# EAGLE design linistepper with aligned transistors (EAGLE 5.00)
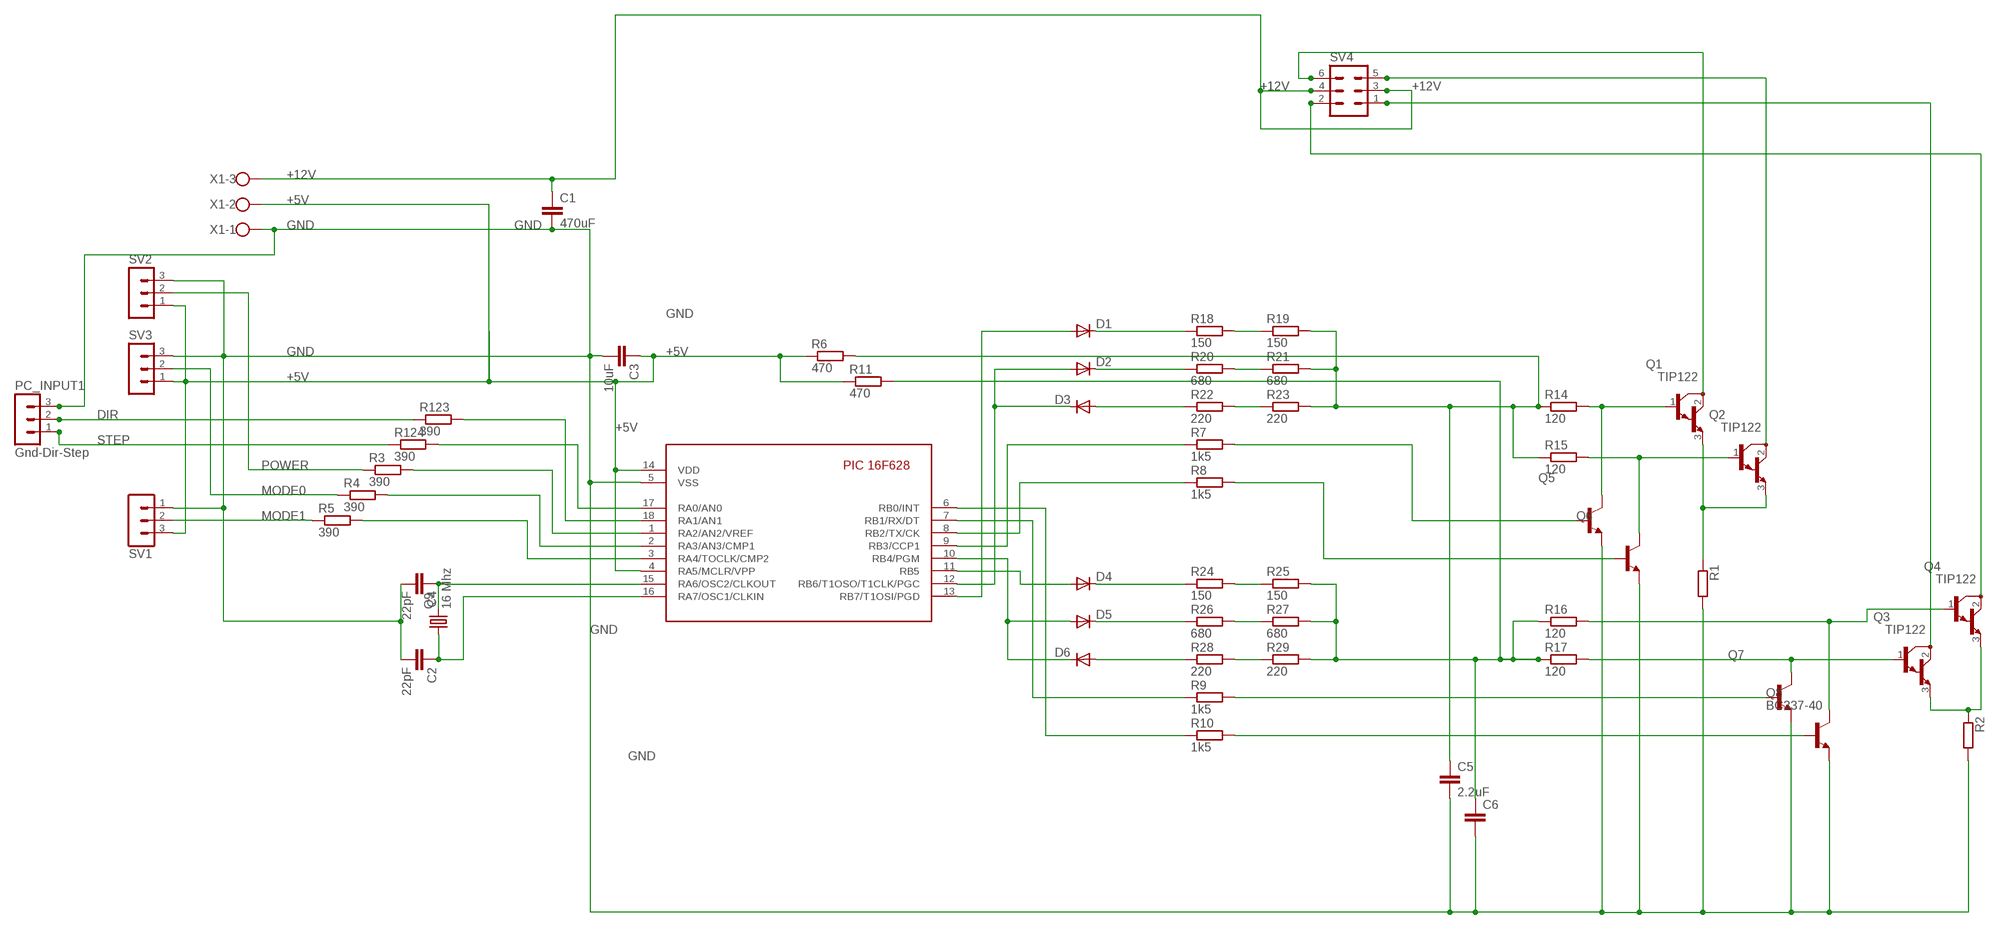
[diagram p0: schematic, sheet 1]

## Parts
C1  470uF  C-EU050-045X075  [C050-045X075]
C2  22pF  C-EU025-024X044  [C025-024X044]
C3  10uF  C-EU025-040X050  [C025-040X050]
C4  22pF  C-EU025-024X044  [C025-024X044]
C5  2.2uF  C-EU050-024X044  [C050-024X044]
C6  C-EU050-024X044  [C050-024X044]
D1  1N4148  [DO35-10]
D2  1N4148  [DO35-10]
D3  1N4148  [DO35-10]
D4  1N4148  [DO35-10]
D5  1N4148  [DO35-10]
D6  1N4148  [DO35-10]
PC_INPUT1  Gnd-Dir-Step  MA03-1  [MA03-1]
Q1  TIP122  [TO220]
Q2  TIP122  [TO220]
Q3  TIP122  [TO220]
Q4  TIP122  [TO220]
Q5  BC337-40  [TO92]
Q6  BC337-40  [TO92]
Q7  BC337-40  [TO92]
Q8  BC337-40  [TO92]
Q9  16 Mhz  CRYTALHC49S  [HC49/S]
R1  R-EU_0922/22  [0922/22]
R2  R-EU_0922/22  [0922/22]
R3  390  R-EU_0204/7  [0204/7]
R4  390  R-EU_0204/7  [0204/7]
R5  390  R-EU_0207/5V  [0207/5V]
R6  470  R-EU_0207/10  [0207/10]
R7  1k5  R-EU_0207/10  [0207/10]
R8  1k5  R-EU_0207/10  [0207/10]
R9  1k5  R-EU_0207/10  [0207/10]
R10  1k5  R-EU_0207/10  [0207/10]
R11  470  R-EU_0207/12  [0207/12]
R14  120  R-EU_0207/10  [0207/10]
R15  120  R-EU_0207/10  [0207/10]
R16  120  R-EU_0207/10  [0207/10]
R17  120  R-EU_0207/10  [0207/10]
R18  150  R-EU_0207/2V  [0207/2V]
R19  150  R-EU_0207/2V  [0207/2V]
R20  680  R-EU_0207/2V  [0207/2V]
R21  680  R-EU_0207/2V  [0207/2V]
R22  220  R-EU_0207/2V  [0207/2V]
R23  220  R-EU_0207/2V  [0207/2V]
R24  150  R-EU_0207/2V  [0207/2V]
R25  150  R-EU_0207/2V  [0207/2V]
R26  680  R-EU_0207/2V  [0207/2V]
R27  680  R-EU_0207/2V  [0207/2V]
R28  220  R-EU_0207/2V  [0207/2V]
R29  220  R-EU_0207/2V  [0207/2V]
R123  390  R-EU_0207/2V  [0207/2V]
R124  390  R-EU_0207/2V  [0207/2V]
SV1  MA03-1  [MA03-1]
SV2  MA03-1  [MA03-1]
SV3  MA03-1  [MA03-1]
SV4  MA03-2  [MA03-2]
U$1  16F628  [PIC16F628-18-LEAD-PDIP]
X1  W237-103  [W237-103]

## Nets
+5V: C3.1 R6.1 R11.1 SV1.3 SV2.1 SV3.1 U$1.4(RA5/MCLR/VPP) U$1.14(VDD) X1.2
+12V: C1.1 SV4.3 SV4.4 X1.3
DIR: PC_INPUT1.2 R123.1
GND: C1.2 C2.2 C3.2 C4.2 C5.2 C6.2 PC_INPUT1.3 Q5.1(E) Q6.1(E) Q7.1(E) Q8.1(E) R1.2 R2.2 SV1.1 SV2.3 SV3.3 U$1.5(VSS) X1.1
MODE0: R4.1 SV3.2
MODE1: R5.1 SV1.2
N$1: R18.2 R19.1
N$2: C5.1 R6.2 R14.1 R15.1 R19.2 R21.2 R23.2
N$3: R20.2 R21.1
N$5: Q1.1(B) Q5.3(C) R14.2
N$6: Q2.1(B) Q6.3(C) R15.2
N$7: D1.C R18.1
N$8: D2.C R20.1
N$9: D3.A R22.1
N$10: D1.A U$1.13(RB7/T1OSI/PGD)
N$11: D2.A D3.C U$1.12(RB6/T1OSO/T1CLK/PGC)
N$12: R8.1 U$1.8(RB2/TX/CK)
N$13: R7.1 U$1.9(RB3/CCP1)
N$14: Q5.2(B) R7.2
N$15: Q6.2(B) R8.2
N$16: Q1.3(E) Q2.3(E) R1.1
N$17: R3.2 U$1.1(RA2/AN2/VREF)
N$18: R4.2 U$1.2(RA3/AN3/CMP1)
N$19: R24.2 R25.1
N$20: D5.C R26.1
N$21: R26.2 R27.1
N$22: D6.A R28.1
N$23: R28.2 R29.1
N$24: D4.A U$1.11(RB5)
N$25: D5.A D6.C U$1.10(RB4/PGM)
N$26: R9.1 U$1.7(RB1/RX/DT)
N$27: R10.1 U$1.6(RB0/INT)
N$28: C6.1 R11.2 R16.1 R17.1 R25.2 R27.2 R29.2
N$29: Q4.1(B) Q8.3(C) R16.2
N$30: Q8.2(B) R10.2
N$31: Q3.1(B) Q7.3(C) R17.2
N$32: Q7.2(B) R9.2
N$33: Q3.3(E) Q4.3(E) R2.1
N$34: Q1.2(C) SV4.6
N$35: Q2.2(C) SV4.5
N$36: Q3.2(C) SV4.1
N$37: Q4.2(C) SV4.2
N$39: R124.2 U$1.17(RA0/AN0)
N$41: R123.2 U$1.18(RA1/AN1)
N$43: C2.1 Q9.1 U$1.16(RA7/OSC1/CLKIN)
N$44: C4.1 Q9.2 U$1.15(RA6/OSC2/CLKOUT)
N$48: R5.2 U$1.3(RA4/TOCLK/CMP2)
POWER: R3.1 SV2.2
R23: R22.2 R23.1
R24: D4.C R24.1
STEP: PC_INPUT1.1 R124.1

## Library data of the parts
C1-C6 = rcl:C-EU: CAPACITOR, European symbol
D1-D6 = diode:1N4148: DIODE
PC_INPUT1 SV1-SV3 = con-lstb:MA03-1: PIN HEADER
Q1-Q4 = transistor-npn:TIP122*: NPN Darlington Transistor
Q5-Q8 = transistor-npn:BC337*: NPN Transistor
Q9 = crystal:CRYTAL: CRYSTAL
R1-R11 R14-R29 R123 R124 = rcl:R-EU_: RESISTOR, European symbol
SV4 = con-lstb:MA03-2: PIN HEADER
U$1 = pic16f6xx:16F628: Microchip component PIC 16F628 Eric Magraner - eric_magraner@yahoo.fr 03/2004
X1 = con-wago-500:W237-103: WAGO SCREW CLAMP

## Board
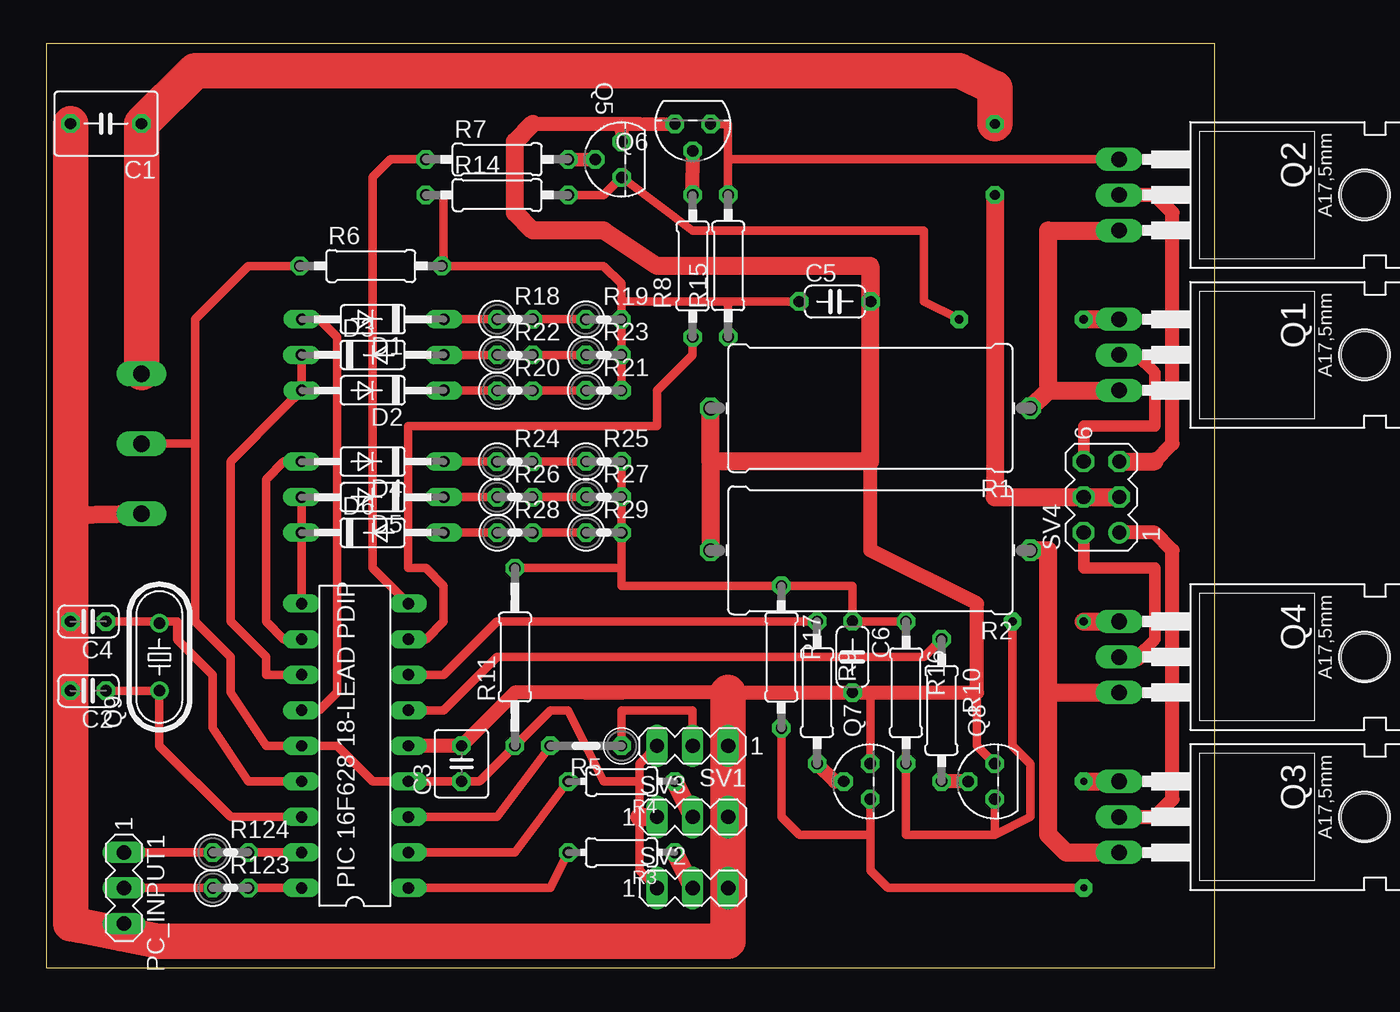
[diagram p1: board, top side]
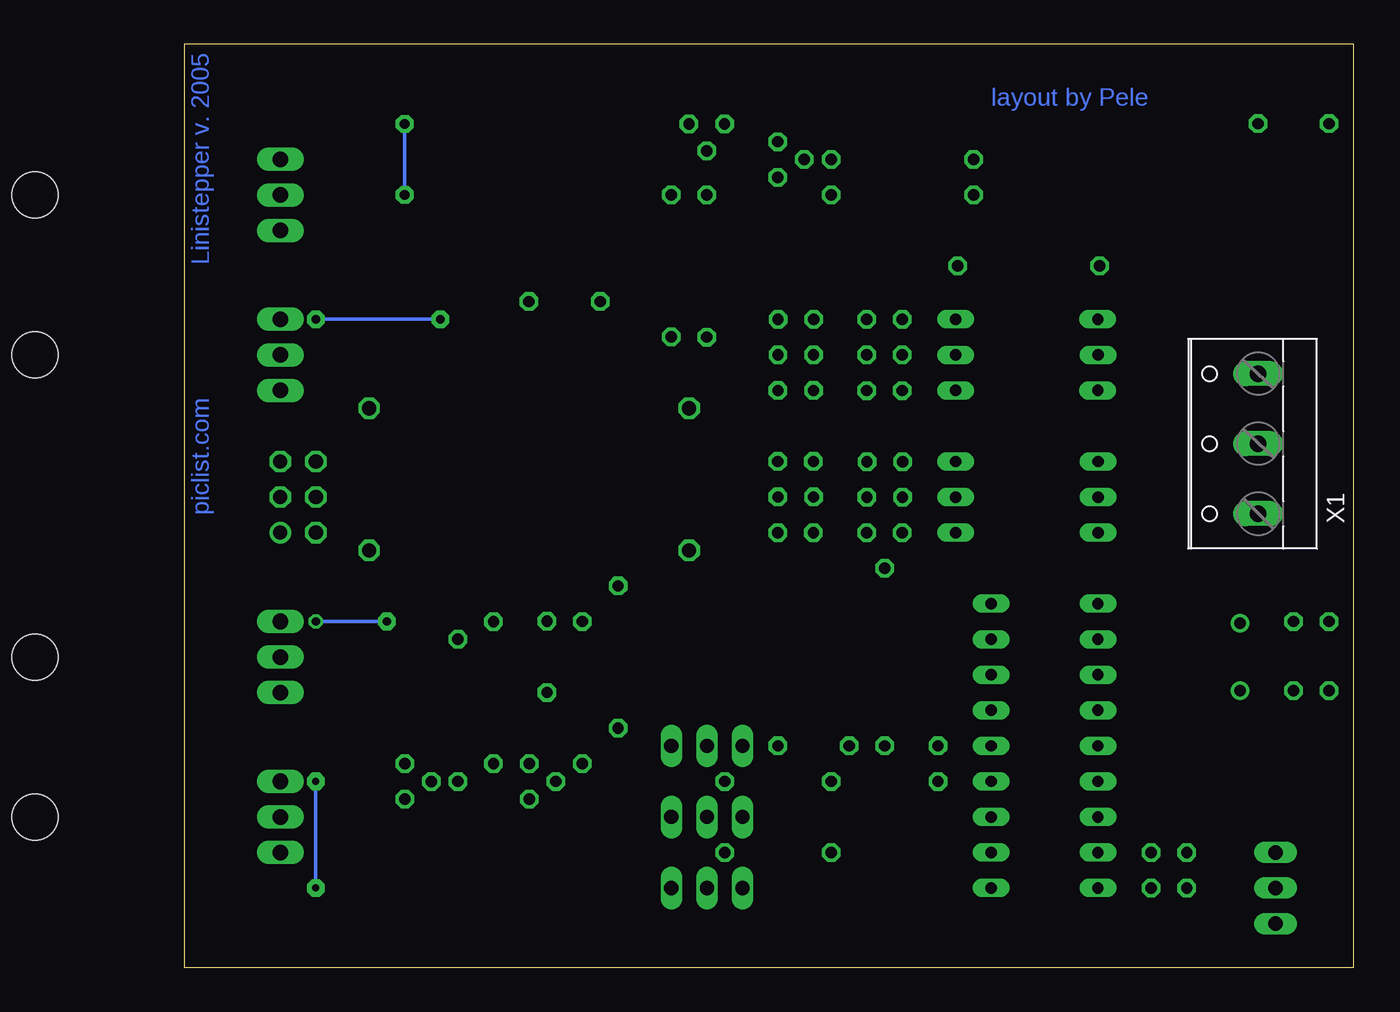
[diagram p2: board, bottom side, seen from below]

Size 83.49 x 66.03 mm. Coordinates in mm from the lower left corner, seen from the top.
Outline: 0,0 83.49,0 83.49,66.03 0,66.03 0,0
Copper layers (1*16): Top 0.035mm / dielectric 1.5mm / Bottom 0.035mm
Design rules "default": minimum track width 10mil, minimum drill 24mil, track to track 8mil, track to pad 8mil, pad to pad 8mil, via to via 8mil, smd to smd 8mil, copper to edge 40mil, drill to drill 8mil, minimum pad ring 10mil, minimum via ring 8mil, stop-mask expansion 4mil, vias tented up to drill 0mil, thermal gap 10mil

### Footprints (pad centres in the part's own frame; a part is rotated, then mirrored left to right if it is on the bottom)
C050-045X075 = drill 0.813 octagon: 1 -2.54,0; 2 2.54,0
C025-024X044 = drill 0.813 octagon: 1 -1.27,0; 2 1.27,0
C025-040X050 = drill 0.813 octagon: 1 -1.27,0; 2 1.27,0
C050-024X044 = drill 0.813 octagon: 1 -2.54,0; 2 2.54,0
DO35-10 = drill 0.813 long: A 5.08,0; C -5.08,0
MA03-1 = drill 1.016 long: 1 -2.54,0; 2 0,0; 3 2.54,0
TO220 = drill 1.118 long: 1 -2.54,-6.35; 2 0,-6.35; 3 2.54,-6.35 | hole 3.302: 0,11.176
TO92 = drill 0.813 octagon: 1 1.27,0; 2 0,1.905; 3 -1.27,0
HC49/S = drill 0.813 round: 1 -2.413,0; 2 2.413,0
0922/22 = drill 1.016 octagon: 1 -11.43,0; 2 11.43,0
0204/7 = drill 0.813 octagon: 1 -3.81,0; 2 3.81,0
0207/5V = drill 0.813 octagon: 1 -2.54,0; 2 2.54,0
0207/10 = drill 0.813 octagon: 1 -5.08,0; 2 5.08,0
0207/12 = drill 0.813 octagon: 1 -6.35,0; 2 6.35,0
0207/2V = drill 0.813 octagon: 1 -1.27,0; 2 1.27,0
MA03-2 = drill 1.016 round: 1 -2.54,-1.27 | drill 1.016 octagon: 2 -2.54,1.27; 3 0,-1.27; 4 0,1.27; 5 2.54,-1.27; 6 2.54,1.27
PIC16F628-18-LEAD-PDIP = drill 0.813 long: 1 -10.16,-3.81; 2 -7.62,-3.81; 3 -5.08,-3.81; 4 -2.54,-3.81; 5 0,-3.81; 6 2.54,-3.81; 7 5.08,-3.81; 8 7.62,-3.81; 9 10.16,-3.81; 10 10.16,3.81; 11 7.62,3.81; 12 5.08,3.81; 13 2.54,3.81; 14 0,3.81; 15 -2.54,3.81; 16 -5.08,3.81; 17 -7.62,3.81; 18 -10.16,3.81
W237-103 = drill 1.194 long: 1 -5,-1.29; 2 0,-1.29; 3 5,-1.29

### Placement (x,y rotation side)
C1  4.27,60.34 180 top
C2  3.01,19.81 180 top
C3  29.68,14.6 90 top
C4  3.01,24.76 180 top
C5  56.36,47.62 0 top
C6  57.61,22.23 270 top
D1  23.34,46.35 180 top
D2  23.33,41.27 180 top
D3  23.32,43.81 0 top
D4  23.33,36.19 180 top
D5  23.33,33.64 180 top
D6  23.32,31.11 0 top
PC_INPUT1  5.55,5.71 270 top
Q1  83.02,43.81 270 top
Q2  83.02,55.24 270 top
Q3  83.02,10.79 270 top
Q4  83.02,22.22 270 top
Q5  41.13,57.77 90.1 top
Q6  46.2,60.3 180 top
Q7  58.89,13.33 90 top
Q8  67.78,13.33 90 top
Q9  8.09,22.22 90 top
R1  58.89,40 180 top
R2  58.89,29.84 180 top
R3  41.11,8.25 180 top
R4  41.11,13.33 180 top
R5  38.57,15.87 180 top
R6  23.2,50.16 0 top
R7  32.22,57.78 0 top
R8  46.19,50.16 90 top
R9  55.08,19.68 270 top
R10  63.97,18.41 270 top
R11  33.49,22.22 90 top
R14  32.22,55.23 0 top
R15  48.73,50.18 90 top
R16  61.43,19.68 270 top
R17  52.53,22.22 270 top
R18  33.49,46.36 0 top
R19  39.84,46.34 0 top
R20  33.49,41.26 0 top
R21  39.84,41.26 0 top
R22  33.5,43.81 0 top
R23  39.84,43.81 0 top
R24  33.48,36.18 0 top
R25  39.85,36.19 0 top
R26  33.49,33.65 0 top
R27  39.84,33.66 0 top
R28  33.49,31.11 0 top
R29  39.84,31.1 0 top
R123  13.17,5.71 0 top
R124  13.17,8.25 0 top
SV1  46.19,15.87 180 top
SV2  46.19,5.71 0 top
SV3  46.19,10.79 0 top
SV4  75.4,33.65 90 top
U$1  22.06,15.87 90 top
X1  8.09,37.46 90 bottom

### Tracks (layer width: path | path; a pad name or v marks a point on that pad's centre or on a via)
+5V
  Top 0.254: R6.1 18.25,50.16
  Top 0.61: R6.1 14.44,50.16 10.63,46.35 10.63,37.46 | 10.63,37.46 X1.2 | 10.63,37.46 10.63,24.76 13.17,22.22 13.17,19.68 15.71,15.87 U$1.14 20.79,15.87 23.33,13.33 U$1.4 C3.1 30.95,13.33 R11.1 36.03,18.41 37.3,18.41 39.84,13.33 42.38,13.33 | SV2.1 42.38,6.98 42.38,10.79 42.38,13.33 | SV1.3 42.38,14.6 42.38,13.33
  Top 1.27: 42.38,10.79 SV3.1
+12V  (via drill 0.6, 0.7 pad 1.27)
  Top 0.254: C1.1
  Top 0.61: X1.3 v6.82,42.54
  Top 1.27: v67.78,55.24 67.78,33.65 SV4.4 SV4.3
  Top 2.54: v6.82,42.54 C1.1 10.63,64.13 65.24,64.13 67.78,62.86 v67.78,60.32
  Bottom 0.254: v67.78,60.32 v67.78,55.24
DIR
  Top 0.61: PC_INPUT1.2 R123.1
GND
  Top 0.254: X1.1 5.55,32.38 | 5.4,2.44 PC_INPUT1.3
  Top 0.406: 48.73,1.9 SV2.3
  Top 0.61: Q7.1 58.89,18.41 58.89,19.68 C6.2 | 66.51,19.68 66.51,15.87 Q8.1 | C1.2
  Top 1.016: U$1.5 C3.2 33.49,19.68 38.57,19.68 | 38.57,19.68 48.73,19.68 58.89,19.68 66.51,19.68 66.51,26.03 58.89,29.84 58.89,36.19 | 38.57,19.68 41.11,19.68 | 41.11,60.32 42.38,60.32 Q6.1 | 41.11,60.32 Q5.1 | 34.76,60.32 41.11,60.32
  Top 1.27: 47.46,36.19 R2.2 | 47.46,36.19 58.89,36.19 58.89,50.16 | 47.46,36.19 R1.2 | 58.89,50.16 C5.2 | 1.74,32.38 X1.1 | 34.76,60.32 33.49,59.05 33.49,53.97 34.76,52.7 39.84,52.7 43.65,50.16 58.89,50.16
  Top 2.54: C1.2 1.74,32.38 C4.2 C2.2 1.74,3.17 5.4,2.44 8.09,1.9 48.73,1.9 SV3.3 SV1.1 48.73,19.68
MODE0
  Top 1.27: SV3.2 R4.1
MODE1
  Top 0.61: SV1.2 46.19,18.41 41.11,18.41 R5.1
N$1
  Top 0.254: R19.1
  Top 0.61: R19.1 R18.2
N$2
  Top 0.254: 48.73,47.62 48.74,46.34 | R21.2 | 39.84,50.16 33.49,50.16 R6.2 | R23.2 R19.2 | R15.1 48.73,46.35
  Top 0.406: 48.73,47.62 R15.1 | R23.2 41.11,42.54
  Top 0.61: 41.11,47.62 48.73,47.62 | R21.2 41.11,42.54 R23.2 | 41.11,47.62 41.11,48.89 39.84,50.16 28.41,50.16 28.41,55.24 R14.1 | 41.11,47.62 R23.2 | 48.73,47.62 48.73,46.35 | 48.73,47.62 C5.1
N$3
  Top 0.254: R21.1
  Top 0.61: R20.2 R21.1
N$5  (via drill 0.6 pad 1.27)
  Top 0.61: R14.2 39.84,55.23 39.84,55.24 41.11,56.51 | 41.11,56.51 46.19,52.7 62.7,52.7 62.7,47.62 v65.24,46.35 | 41.11,56.51 Q5.3
  Top 1.27: v74.13,46.35 Q1.1
  Bottom 0.254: v65.24,46.35 v74.13,46.35
N$6
  Top 0.61: R15.2 48.73,57.78 | Q6.3 48.72,60.3 48.73,57.78 | 48.73,57.78 Q2.1
N$7
  Top 0.61: D1.C 29.68,46.35 30.95,46.35 R18.1
N$8
  Top 0.61: D2.C 29.68,41.27 30.95,41.27 R20.1
N$9
  Top 0.61: R22.1 30.95,43.81 29.68,43.81 D3.A
N$10
  Top 0.61: U$1.13 19.52,18.41 20.79,19.68 20.79,45.08 19.52,46.35 D1.A
N$11
  Top 0.254: D2.A
  Top 0.61: D2.A 18.25,42.54 D3.C | U$1.12 15.71,20.95 15.71,22.22 13.17,24.76 13.17,36.19 16.98,40 D2.A
N$12
  Top 0.61: U$1.8 27.14,23.49 28.41,24.76 28.41,27.3 27.14,28.57 25.87,28.57 25.87,38.73 43.65,38.73 43.65,41.27 46.19,43.81 R8.1
N$13
  Top 0.61: U$1.9 23.33,28.57 23.33,56.51 24.6,57.78 R7.1
N$14
  Top 1.016: R7.2 Q5.2
N$15
  Top 1.016: R8.2 Q6.2
N$16
  Top 1.27: 71.59,41.27 Q1.3 | R1.1 71.59,41.27 | 71.59,41.27 71.59,52.7 Q2.3
N$17
  Top 0.61: U$1.1 36.03,5.71 R3.2
N$18
  Top 0.61: U$1.2 33.49,8.25 R4.2
N$19
  Top 0.254: R25.1
  Top 0.61: R24.2 R25.1
N$20
  Top 0.61: D5.C 29.68,33.65 30.95,33.65 R26.1
N$21
  Top 0.254: R27.1
  Top 0.61: R26.2 R27.1
N$22
  Top 0.61: D6.A 29.68,31.11 30.95,31.11 R28.1
N$23
  Top 0.254: R29.1
  Top 0.61: R28.2 R29.1
N$24
  Top 0.61: U$1.11 16.98,23.49 15.71,24.76 15.71,34.92 16.98,36.19 D4.A
N$25
  Top 0.254: D5.A | D6.C
  Top 0.61: U$1.10 D6.C D5.A
N$26
  Top 0.61: U$1.7 28.41,20.95 32.22,24.76 R9.1
N$27
  Top 0.61: R10.1 62.7,22.22 32.22,22.22 28.41,18.41 U$1.6
N$28
  Top 0.254: R25.2 | R29.2 | C6.1
  Top 0.61: R25.2 R27.2 R29.2 41.11,28.57 | R16.1 C6.1 57.62,27.3 | 57.62,27.3 R17.1 | R11.2 41.11,28.57 | 41.11,28.57 41.11,27.3 57.62,27.3
N$29  (via drill 0.6 pad 0.81, 0.6 pad 1.27)
  Top 0.61: 67.78,9.52 61.43,9.52 R16.2 | 67.78,9.52 Q8.3 | 67.78,9.52 70.32,10.79 70.32,14.6 69.05,15.87 v69.05,24.76
  Top 1.27: v74.13,24.76 Q4.1
  Bottom 0.254: v69.05,24.76 v74.13,24.76
N$30
  Top 0.61: R10.2
  Top 1.016: Q8.2 R10.2
N$31  (via drill 0.5 pad 1.27)
  Top 0.61: 58.89,9.52 53.81,9.52 52.54,10.79 R17.2 | 58.89,9.52 Q7.3 | 58.89,9.52 58.89,6.98 60.16,5.71 v74.13,5.71
  Top 1.27: v74.13,13.33 Q3.1
  Bottom 0.254: v74.13,5.71 v74.13,13.33
N$32
  Top 0.61: 56.35,13.33 Q7.2 | R9.2 55.71,13.97
  Top 1.016: R9.2 56.35,13.33
N$33
  Top 1.27: 71.59,19.68 71.59,29.84 R2.1 | 71.59,19.68 71.59,9.52 72.86,8.25 Q3.3 | 71.59,19.68 Q4.3
N$34
  Top 0.813: Q1.2 77.94,43.81 79.21,42.54 79.21,38.73 74.13,38.73 SV4.6
N$35
  Top 1.016: 79.21,36.19 80.48,37.46 80.48,53.97 79.21,55.24 Q2.2
  Top 1.27: SV4.5 79.21,36.19
N$36
  Top 1.016: Q3.2 79.21,10.79 80.48,12.06 80.48,29.84 79.21,31.11 SV4.1
N$37
  Top 0.813: 77.94,22.22 79.21,23.49 79.21,28.57 74.13,28.57 SV4.2
  Top 1.27: Q4.2 77.94,22.22
N$39
  Top 0.61: R124.2 U$1.17
N$41
  Top 0.61: R123.2 U$1.18
N$43
  Top 0.406: 5.54,19.8 Q9.1
  Top 0.61: U$1.16 13.17,10.79 8.09,15.87 8.08,19.8 5.54,19.8 C2.1
N$44
  Top 0.254: 9.36,24.76 Q9.2
  Top 0.61: C4.1 9.36,24.76 9.36,23.49 11.9,20.95 11.9,17.14 14.44,13.33 U$1.15
N$48
  Top 0.61: U$1.3 32.22,10.79 R5.2
POWER
  Top 1.27: SV2.2 R3.1
R23
  Top 0.254: R23.1
  Top 0.61: R22.2 R23.1
R24
  Top 0.61: D4.C 29.68,36.19 30.95,36.19 R24.1
STEP
  Top 0.61: PC_INPUT1.1 R124.1

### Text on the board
Bottom: Linistepper v. 2005 | layout by Pele | piclist.com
